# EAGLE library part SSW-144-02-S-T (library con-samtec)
THROUGH-HOLE .025" SQ POST SOCKET Source: Samtec SSW.pdf
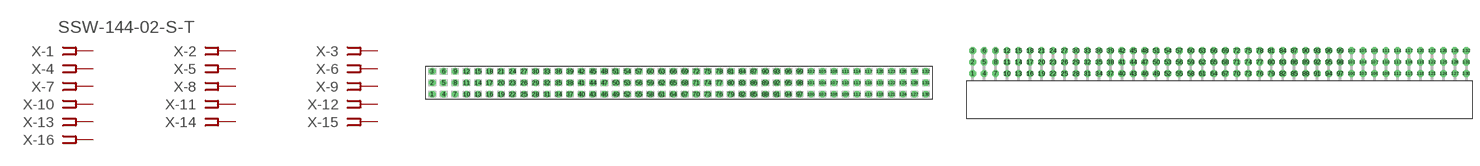
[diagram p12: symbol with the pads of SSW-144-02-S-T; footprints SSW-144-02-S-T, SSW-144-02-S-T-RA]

Designator prefix X; gates -1=FPINV -2=FPIN -3=FPIN -4=FPIN -5=FPIN -6=FPIN -7=FPIN -8=FPIN -9=FPIN -10=FPIN -11=FPIN -12=FPIN -13=FPIN -14=FPIN -15=FPIN -16=FPIN -17=FPIN -18=FPIN -19=FPIN -20=FPIN -21=FPIN -22=FPIN -23=FPIN -24=FPIN -25=FPIN -26=FPIN -27=FPIN -28=FPIN -29=FPIN -30=FPIN -31=FPIN -32=FPIN -33=FPIN -34=FPIN -35=FPIN -36=FPIN -37=FPIN -38=FPIN -39=FPIN -40=FPIN -41=FPIN -42=FPIN -43=FPIN -44=FPIN -45=FPIN -46=FPIN -47=FPIN -48=FPIN -49=FPIN -50=FPIN -51=FPIN -52=FPIN -53=FPIN -54=FPIN -55=FPIN -56=FPIN -57=FPIN -58=FPIN -59=FPIN -60=FPIN -61=FPIN -62=FPIN -63=FPIN -64=FPIN -65=FPIN -66=FPIN -67=FPIN -68=FPIN -69=FPIN -70=FPIN -71=FPIN -72=FPIN -73=FPIN -74=FPIN -75=FPIN -76=FPIN -77=FPIN -78=FPIN -79=FPIN -80=FPIN -81=FPIN -82=FPIN -83=FPIN -84=FPIN -85=FPIN -86=FPIN -87=FPIN -88=FPIN -89=FPIN -90=FPIN -91=FPIN -92=FPIN -93=FPIN -94=FPIN -95=FPIN -96=FPIN -97=FPIN -98=FPIN -99=FPIN -100=FPIN -101=FPIN -102=FPIN -103=FPIN -104=FPIN -105=FPIN -106=FPIN -107=FPIN -108=FPIN -109=FPIN -110=FPIN -111=FPIN -112=FPIN -113=FPIN -114=FPIN -115=FPIN -116=FPIN -117=FPIN -118=FPIN -119=FPIN -120=FPIN -121=FPIN -122=FPIN -123=FPIN -124=FPIN -125=FPIN -126=FPIN -127=FPIN -128=FPIN -129=FPIN -130=FPIN -131=FPIN -132=FPIN

## SSW-144-02-S-T (OC_FARNELL: unknown; OC_NEWARK: unknown)  [SSW-144-02-S-T]
1  -1:1  pas
2  -2:1  pas
3  -3:1  pas
4  -4:1  pas
5  -5:1  pas
6  -6:1  pas
7  -7:1  pas
8  -8:1  pas
9  -9:1  pas
10  -10:1  pas
11  -11:1  pas
12  -12:1  pas
13  -13:1  pas
14  -14:1  pas
15  -15:1  pas
16  -16:1  pas
17  -17:1  pas
18  -18:1  pas
19  -19:1  pas
20  -20:1  pas
21  -21:1  pas
22  -22:1  pas
23  -23:1  pas
24  -24:1  pas
25  -25:1  pas
26  -26:1  pas
27  -27:1  pas
28  -28:1  pas
29  -29:1  pas
30  -30:1  pas
31  -31:1  pas
32  -32:1  pas
33  -33:1  pas
34  -34:1  pas
35  -35:1  pas
36  -36:1  pas
37  -37:1  pas
38  -38:1  pas
39  -39:1  pas
40  -40:1  pas
41  -41:1  pas
42  -42:1  pas
43  -43:1  pas
44  -44:1  pas
45  -45:1  pas
46  -46:1  pas
47  -47:1  pas
48  -48:1  pas
49  -49:1  pas
50  -50:1  pas
51  -51:1  pas
52  -52:1  pas
53  -53:1  pas
54  -54:1  pas
55  -55:1  pas
56  -56:1  pas
57  -57:1  pas
58  -58:1  pas
59  -59:1  pas
60  -60:1  pas
61  -61:1  pas
62  -62:1  pas
63  -63:1  pas
64  -64:1  pas
65  -65:1  pas
66  -66:1  pas
67  -67:1  pas
68  -68:1  pas
69  -69:1  pas
70  -70:1  pas
71  -71:1  pas
72  -72:1  pas
73  -73:1  pas
74  -74:1  pas
75  -75:1  pas
76  -76:1  pas
77  -77:1  pas
78  -78:1  pas
79  -79:1  pas
80  -80:1  pas
81  -81:1  pas
82  -82:1  pas
83  -83:1  pas
84  -84:1  pas
85  -85:1  pas
86  -86:1  pas
87  -87:1  pas
88  -88:1  pas
89  -89:1  pas
90  -90:1  pas
91  -91:1  pas
92  -92:1  pas
93  -93:1  pas
94  -94:1  pas
95  -95:1  pas
96  -96:1  pas
97  -97:1  pas
98  -98:1  pas
99  -99:1  pas
100  -100:1  pas
101  -101:1  pas
102  -102:1  pas
103  -103:1  pas
104  -104:1  pas
105  -105:1  pas
106  -106:1  pas
107  -107:1  pas
108  -108:1  pas
109  -109:1  pas
110  -110:1  pas
111  -111:1  pas
112  -112:1  pas
113  -113:1  pas
114  -114:1  pas
115  -115:1  pas
116  -116:1  pas
117  -117:1  pas
118  -118:1  pas
119  -119:1  pas
120  -120:1  pas
121  -121:1  pas
122  -122:1  pas
123  -123:1  pas
124  -124:1  pas
125  -125:1  pas
126  -126:1  pas
127  -127:1  pas
128  -128:1  pas
129  -129:1  pas
130  -130:1  pas
131  -131:1  pas
132  -132:1  pas

## SSW-144-02-S-TRA (OC_FARNELL: unknown; OC_NEWARK: unknown)  [SSW-144-02-S-T-RA]
Pads as for SSW-144-02-S-T

## Footprint SSW-144-02-S-T (pad centres in mm)
THROUGH-HOLE .025" SQ POST SOCKET Source: Samtec SSW.pdf
drill 1 pad 1.5 octagon: 1 -54.61,-2.54; 2 -54.61,0; 3 -54.61,2.54; 4 -52.07,-2.54; 5 -52.07,0; 6 -52.07,2.54; 7 -49.53,-2.54; 8 -49.53,0; 9 -49.53,2.54; 10 -46.99,-2.54; 11 -46.99,0; 12 -46.99,2.54; 13 -44.45,-2.54; 14 -44.45,0; 15 -44.45,2.54; 16 -41.91,-2.54; 17 -41.91,0; 18 -41.91,2.54; 19 -39.37,-2.54; 20 -39.37,0; 21 -39.37,2.54; 22 -36.83,-2.54; 23 -36.83,0; 24 -36.83,2.54; 25 -34.29,-2.54; 26 -34.29,0; 27 -34.29,2.54; 28 -31.75,-2.54; 29 -31.75,0; 30 -31.75,2.54; 31 -29.21,-2.54; 32 -29.21,0; 33 -29.21,2.54; 34 -26.67,-2.54; 35 -26.67,0; 36 -26.67,2.54; 37 -24.13,-2.54; 38 -24.13,0; 39 -24.13,2.54; 40 -21.59,-2.54; 41 -21.59,0; 42 -21.59,2.54; 43 -19.05,-2.54; 44 -19.05,0; 45 -19.05,2.54; 46 -16.51,-2.54; 47 -16.51,0; 48 -16.51,2.54; 49 -13.97,-2.54; 50 -13.97,0; 51 -13.97,2.54; 52 -11.43,-2.54; 53 -11.43,0; 54 -11.43,2.54; 55 -8.89,-2.54; 56 -8.89,0; 57 -8.89,2.54; 58 -6.35,-2.54; 59 -6.35,0; 60 -6.35,2.54; 61 -3.81,-2.54; 62 -3.81,0; 63 -3.81,2.54; 64 -1.27,-2.54; 65 -1.27,0; 66 -1.27,2.54; 67 1.27,-2.54; 68 1.27,0; 69 1.27,2.54; 70 3.81,-2.54; 71 3.81,0; 72 3.81,2.54; 73 6.35,-2.54; 74 6.35,0; 75 6.35,2.54; 76 8.89,-2.54; 77 8.89,0; 78 8.89,2.54; 79 11.43,-2.54; 80 11.43,0; 81 11.43,2.54; 82 13.97,-2.54; 83 13.97,0; 84 13.97,2.54; 85 16.51,-2.54; 86 16.51,0; 87 16.51,2.54; 88 19.05,-2.54; 89 19.05,0; 90 19.05,2.54; 91 21.59,-2.54; 92 21.59,0; 93 21.59,2.54; 94 24.13,-2.54; 95 24.13,0; 96 24.13,2.54; 97 26.67,-2.54; 98 26.67,0; 99 26.67,2.54; 100 29.21,-2.54; 101 29.21,0; 102 29.21,2.54; 103 31.75,-2.54; 104 31.75,0; 105 31.75,2.54; 106 34.29,-2.54; 107 34.29,0; 108 34.29,2.54; 109 36.83,-2.54; 110 36.83,0; 111 36.83,2.54; 112 39.37,-2.54; 113 39.37,0; 114 39.37,2.54; 115 41.91,-2.54; 116 41.91,0; 117 41.91,2.54; 118 44.45,-2.54; 119 44.45,0; 120 44.45,2.54; 121 46.99,-2.54; 122 46.99,0; 123 46.99,2.54; 124 49.53,-2.54; 125 49.53,0; 126 49.53,2.54; 127 52.07,-2.54; 128 52.07,0; 129 52.07,2.54; 130 54.61,-2.54; 131 54.61,0; 132 54.61,2.54

## Footprint SSW-144-02-S-T-RA (pad centres in mm)
THROUGH-HOLE .025" SQ POST SOCKET Source: Samtec SSW.pdf
drill 1 pad 1.5 octagon: 1 -54.61,1.524; 2 -54.61,4.064; 3 -54.61,6.604; 4 -52.07,1.524; 5 -52.07,4.064; 6 -52.07,6.604; 7 -49.53,1.524; 8 -49.53,4.064; 9 -49.53,6.604; 10 -46.99,1.524; 11 -46.99,4.064; 12 -46.99,6.604; 13 -44.45,1.524; 14 -44.45,4.064; 15 -44.45,6.604; 16 -41.91,1.524; 17 -41.91,4.064; 18 -41.91,6.604; 19 -39.37,1.524; 20 -39.37,4.064; 21 -39.37,6.604; 22 -36.83,1.524; 23 -36.83,4.064; 24 -36.83,6.604; 25 -34.29,1.524; 26 -34.29,4.064; 27 -34.29,6.604; 28 -31.75,1.524; 29 -31.75,4.064; 30 -31.75,6.604; 31 -29.21,1.524; 32 -29.21,4.064; 33 -29.21,6.604; 34 -26.67,1.524; 35 -26.67,4.064; 36 -26.67,6.604; 37 -24.13,1.524; 38 -24.13,4.064; 39 -24.13,6.604; 40 -21.59,1.524; 41 -21.59,4.064; 42 -21.59,6.604; 43 -19.05,1.524; 44 -19.05,4.064; 45 -19.05,6.604; 46 -16.51,1.524; 47 -16.51,4.064; 48 -16.51,6.604; 49 -13.97,1.524; 50 -13.97,4.064; 51 -13.97,6.604; 52 -11.43,1.524; 53 -11.43,4.064; 54 -11.43,6.604; 55 -8.89,1.524; 56 -8.89,4.064; 57 -8.89,6.604; 58 -6.35,1.524; 59 -6.35,4.064; 60 -6.35,6.604; 61 -3.81,1.524; 62 -3.81,4.064; 63 -3.81,6.604; 64 -1.27,1.524; 65 -1.27,4.064; 66 -1.27,6.604; 67 1.27,1.524; 68 1.27,4.064; 69 1.27,6.604; 70 3.81,1.524; 71 3.81,4.064; 72 3.81,6.604; 73 6.35,1.524; 74 6.35,4.064; 75 6.35,6.604; 76 8.89,1.524; 77 8.89,4.064; 78 8.89,6.604; 79 11.43,1.524; 80 11.43,4.064; 81 11.43,6.604; 82 13.97,1.524; 83 13.97,4.064; 84 13.97,6.604; 85 16.51,1.524; 86 16.51,4.064; 87 16.51,6.604; 88 19.05,1.524; 89 19.05,4.064; 90 19.05,6.604; 91 21.59,1.524; 92 21.59,4.064; 93 21.59,6.604; 94 24.13,1.524; 95 24.13,4.064; 96 24.13,6.604; 97 26.67,1.524; 98 26.67,4.064; 99 26.67,6.604; 100 29.21,1.524; 101 29.21,4.064; 102 29.21,6.604; 103 31.75,1.524; 104 31.75,4.064; 105 31.75,6.604; 106 34.29,1.524; 107 34.29,4.064; 108 34.29,6.604; 109 36.83,1.524; 110 36.83,4.064; 111 36.83,6.604; 112 39.37,1.524; 113 39.37,4.064; 114 39.37,6.604; 115 41.91,1.524; 116 41.91,4.064; 117 41.91,6.604; 118 44.45,1.524; 119 44.45,4.064; 120 44.45,6.604; 121 46.99,1.524; 122 46.99,4.064; 123 46.99,6.604; 124 49.53,1.524; 125 49.53,4.064; 126 49.53,6.604; 127 52.07,1.524; 128 52.07,4.064; 129 52.07,6.604; 130 54.61,1.524; 131 54.61,4.064; 132 54.61,6.604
